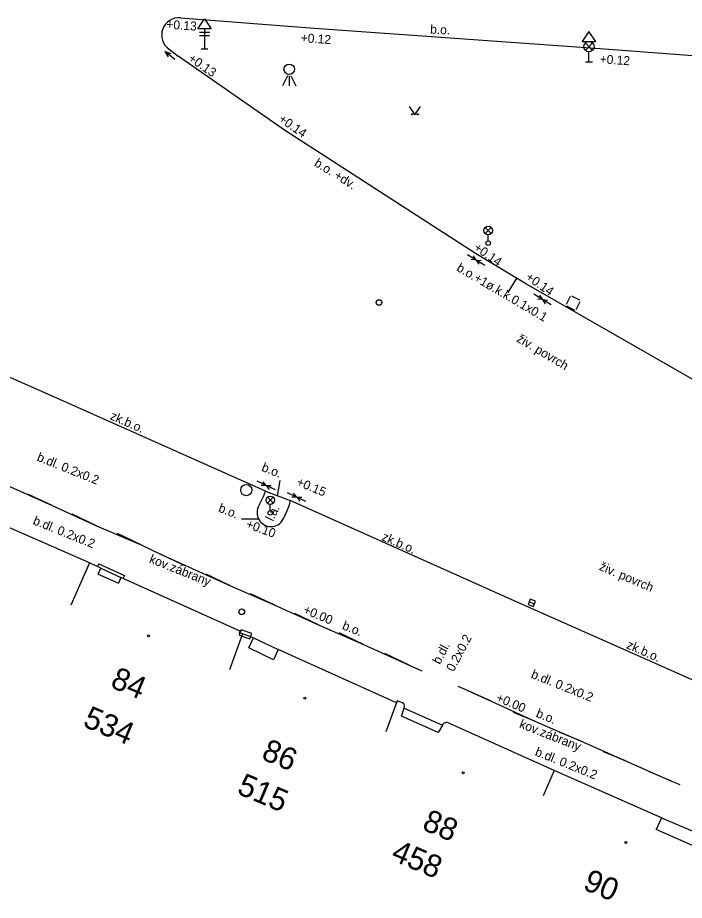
# Model space of a CAD drawing. Extents: x -596069 to -595683, y -1161832 to -1161593.
# Drawn here: x -596003.49 to -595973.78, y -1161680.47 to -1161641.11 of the extents above; entities that cross this region are included whole.
import ezdxf

# ---------------------------------------------------------------- set-up
doc = ezdxf.new("R2010")
doc.units = 0
for name, color, linetype in [('Vrstva 14', 7, 'Continuous'), ('Vrstva 15', 7, 'Continuous'), ('Vrstva 23', 7, 'Continuous'), ('Vrstva 24', 7, 'Continuous'), ('Vrstva 25', 7, 'Continuous'), ('Vrstva 29', 7, 'Continuous'), ('Vrstva 4', 7, 'Continuous'), ('Vrstva 43', 7, 'Continuous'), ('Vrstva 44', 7, 'Continuous'), ('Vrstva 49', 7, 'Continuous'), ('Vrstva 5', 7, 'Continuous'), ('Vrstva 50', 7, 'Continuous'), ('Vrstva 7', 7, 'Continuous')]:
    doc.layers.add(name, color=color, linetype=linetype)

msp = doc.modelspace()

# ---------------------------------------------------------------- linework, layer by layer
at = {"layer": 'Vrstva 14'}
msp.add_lwpolyline([(-595986.039, -1161645.069), (-595985.789, -1161645.444), (-595985.539, -1161645.069)], dxfattribs=at)
for centre in [(-595985.914, -1161645.419), (-595985.664, -1161645.419)]:
    msp.add_circle(centre, 0.025, dxfattribs=at)
at = {"layer": 'Vrstva 15'}
for centre in [(-595997.659, -1161668.68), (-595990.699, -1161671.454), (-595983.641, -1161674.788), (-595976.389, -1161677.888)]:
    msp.add_circle(centre, 0.0438, dxfattribs=at)
at = {"layer": 'Vrstva 23'}
for p, q in [((-595978.866, -1161653.544), (-595979.05, -1161653.899)), ((-595978.443, -1161653.706), (-595978.799, -1161653.523)), ((-595979.028, -1161653.967), (-595978.673, -1161654.15)), ((-595978.606, -1161654.129), (-595978.422, -1161653.774))]:
    msp.add_line(p, q, dxfattribs=at)
msp.add_circle((-595987.39, -1161653.81), 0.125, dxfattribs=at)
at = {"layer": 'Vrstva 24'}
msp.add_circle((-595993.506, -1161667.602), 0.125, dxfattribs=at)
at = {"layer": 'Vrstva 25'}
msp.add_line((-595980.695, -1161667.161), (-595980.463, -1161667.253), dxfattribs=at)
msp.add_lwpolyline([(-595980.741, -1161667.278), (-595980.508, -1161667.369), (-595980.417, -1161667.136), (-595980.65, -1161667.045)], close=True, dxfattribs=at)
msp.add_circle((-595993.304, -1161662.176), 0.25, dxfattribs=at)
at = {"layer": 'Vrstva 29'}
for p, q in [((-595982.656, -1161650.732), (-595982.392, -1161650.468)), ((-595982.388, -1161650.731), (-595982.652, -1161650.466)), ((-595982.524, -1161651.063), (-595982.524, -1161650.788)), ((-595992.366, -1161662.76), (-595992.102, -1161662.496)), ((-595992.098, -1161662.759), (-595992.362, -1161662.494)), ((-595992.234, -1161663.091), (-595992.234, -1161662.816))]:
    msp.add_line(p, q, dxfattribs=at)
msp.add_lwpolyline([(-595993.617, -1161668.642), (-595993.147, -1161668.813), (-595993.061, -1161668.578), (-595993.531, -1161668.407)], close=True, dxfattribs=at)
for centre, radius in [((-595982.524, -1161650.6), 0.188), ((-595982.524, -1161651.163), 0.1), ((-595992.234, -1161662.629), 0.188), ((-595992.234, -1161663.191), 0.1)]:
    msp.add_circle(centre, radius, dxfattribs=at)
at = {"layer": 'Vrstva 4'}
for p, q in [((-596000.293, -1161665.422), (-596004.908, -1161663.397)), ((-595999.782, -1161665.657), (-596000.293, -1161665.422)), ((-595999.901, -1161665.919), (-595999.781, -1161665.655)), ((-595998.888, -1161666.067), (-595999.004, -1161666.324)), ((-595993.583, -1161668.471), (-595998.888, -1161666.067)), ((-595993.583, -1161668.471), (-595993.616, -1161668.544)), ((-595993.471, -1161668.584), (-595993.616, -1161668.544)), ((-595993.471, -1161668.584), (-595994.047, -1161670.189))]:
    msp.add_line(p, q, dxfattribs=at)
for points in [[(-596000.293, -1161665.422), (-596001.12, -1161667.308)], [(-595999.87, -1161665.461), (-595999.928, -1161665.588)], [(-595999.87, -1161665.461), (-595998.739, -1161665.982)], [(-595999.781, -1161665.655), (-595998.888, -1161666.067)], [(-595998.739, -1161665.982), (-595998.794, -1161666.103)], [(-595992.975, -1161668.762), (-595993.471, -1161668.584)], [(-595993.192, -1161669.213), (-595992.975, -1161668.762)], [(-595992.975, -1161668.762), (-595991.89, -1161669.283)], [(-595991.89, -1161669.283), (-595992.096, -1161669.739)], [(-595986.614, -1161671.669), (-595991.89, -1161669.283)], [(-595986.58, -1161671.575), (-595987.078, -1161672.953)], [(-595986.337, -1161671.663), (-595986.58, -1161671.575)], [(-595986.389, -1161672.252), (-595986.269, -1161671.893)], [(-595986.269, -1161671.893), (-595984.566, -1161672.655)], [(-595984.566, -1161672.655), (-595984.757, -1161672.989)], [(-595979.585, -1161674.683), (-595984.275, -1161672.575)], [(-595979.585, -1161674.683), (-595980.078, -1161675.805)], [(-595974.8, -1161676.786), (-595979.585, -1161674.683)], [(-595974.8, -1161676.786), (-595975.033, -1161677.317)], [(-595974.8, -1161676.786), (-595972.91, -1161677.594)]]:
    msp.add_lwpolyline(points, dxfattribs=at)
for centre, radius, start, end in [((-595986.42, -1161671.813), 0.171, 331.9529, 60.988), ((-595984.384, -1161672.748), 0.205, 57.8678, 152.8755)]:
    msp.add_arc(centre, radius, start, end, dxfattribs=at)
at = {"layer": 'Vrstva 44'}
for p, q in [((-595995.382, -1161641.756), (-595994.934, -1161641.756)), ((-595995.162, -1161641.606), (-595995.162, -1161642.506)), ((-595995.382, -1161641.906), (-595994.939, -1161641.906)), ((-595995.312, -1161642.506), (-595995.012, -1161642.506)), ((-595977.88, -1161642.232), (-595978.18, -1161642.576)), ((-595978.18, -1161642.232), (-595977.88, -1161642.576)), ((-595978.03, -1161643.082), (-595978.03, -1161642.632)), ((-595978.18, -1161643.082), (-595977.88, -1161643.082)), ((-595991.466, -1161643.705), (-595991.692, -1161644.157)), ((-595991.392, -1161643.707), (-595991.392, -1161644.157)), ((-595991.317, -1161643.705), (-595991.092, -1161644.157)), ((-596001.954, -1161662.87), (-596003.041, -1161662.353)), ((-595999.975, -1161663.763), (-596001.062, -1161663.246)), ((-595997.953, -1161664.626), (-595999.04, -1161664.109)), ((-595996.044, -1161665.555), (-595997.131, -1161665.038)), ((-595994.007, -1161666.448), (-595995.094, -1161665.931)), ((-595992.025, -1161667.312), (-595993.112, -1161666.795)), ((-595990.056, -1161668.196), (-595991.143, -1161667.679)), ((-595988.083, -1161669.062), (-595989.17, -1161668.545)), ((-595986.049, -1161669.986), (-595987.136, -1161669.469)), ((-595982.389, -1161671.59), (-595983.45, -1161671.116)), ((-595980.409, -1161672.491), (-595981.389, -1161672.089)), ((-595978.385, -1161673.366), (-595979.365, -1161672.964)), ((-595976.402, -1161674.248), (-595977.382, -1161673.846)), ((-595974.35, -1161675.148), (-595975.33, -1161674.746))]:
    msp.add_line(p, q, dxfattribs=at)
msp.add_lwpolyline([(-595995.462, -1161641.611), (-595995.162, -1161641.156), (-595994.862, -1161641.611)], close=True, dxfattribs=at)
msp.add_lwpolyline([(-595978.33, -1161642.176), (-595977.73, -1161642.176), (-595978.03, -1161641.726), (-595978.33, -1161642.176)], dxfattribs=at)
for centre, radius in [((-595978.03, -1161642.404), 0.228), ((-595991.392, -1161643.412), 0.234)]:
    msp.add_circle(centre, radius, dxfattribs=at)
at = {"layer": 'Vrstva 49'}
for p, q in [((-595996.489, -1161642.971), (-595996.928, -1161642.617)), ((-595996.928, -1161642.617), (-595996.661, -1161642.707)), ((-595996.928, -1161642.617), (-595996.78, -1161642.858)), ((-595982.679, -1161652.158), (-595983.443, -1161651.68)), ((-595983.061, -1161651.919), (-595983.284, -1161651.897)), ((-595983.061, -1161651.919), (-595983.179, -1161651.73)), ((-595983.061, -1161651.919), (-595982.946, -1161652.108)), ((-595983.061, -1161651.919), (-595982.839, -1161651.94)), ((-595981.265, -1161652.729), (-595981.652, -1161653.359)), ((-595979.717, -1161653.918), (-595980.481, -1161653.44)), ((-595980.099, -1161653.679), (-595980.217, -1161653.49)), ((-595980.099, -1161653.679), (-595980.322, -1161653.657)), ((-595980.099, -1161653.679), (-595979.984, -1161653.868)), ((-595980.099, -1161653.679), (-595979.877, -1161653.7)), ((-595992.009, -1161662.171), (-595992.821, -1161661.781)), ((-595992.415, -1161661.976), (-595992.553, -1161661.801)), ((-595991.908, -1161662.433), (-595991.79, -1161661.744)), ((-595992.415, -1161661.976), (-595992.639, -1161661.978)), ((-595992.415, -1161661.976), (-595992.192, -1161661.972)), ((-595992.415, -1161661.976), (-595992.28, -1161662.152)), ((-595990.65, -1161662.684), (-595991.462, -1161662.294)), ((-595991.056, -1161662.489), (-595991.28, -1161662.491)), ((-595991.056, -1161662.489), (-595991.194, -1161662.314)), ((-595991.056, -1161662.489), (-595990.833, -1161662.485)), ((-595991.056, -1161662.489), (-595990.921, -1161662.665)), ((-595992.755, -1161663.477), (-595993.523, -1161663.477))]:
    msp.add_line(p, q, dxfattribs=at)
at = {"layer": 'Vrstva 5'}
for p, q in [((-595999.901, -1161665.919), (-595999.004, -1161666.324)), ((-595992.096, -1161669.739), (-595993.192, -1161669.213)), ((-595984.757, -1161672.989), (-595986.389, -1161672.252)), ((-595973.15, -1161678.142), (-595975.033, -1161677.317))]:
    msp.add_line(p, q, dxfattribs=at)
at = {"layer": 'Vrstva 7'}
for p, q in [((-596003.946, -1161661.974), (-596001.954, -1161662.87)), ((-595992.446, -1161662.231), (-595991.352, -1161662.644)), ((-596001.954, -1161662.87), (-595999.975, -1161663.763)), ((-595999.975, -1161663.763), (-595997.953, -1161664.626)), ((-595997.953, -1161664.626), (-595997.131, -1161665.038)), ((-595997.131, -1161665.038), (-595994.007, -1161666.448)), ((-595986.049, -1161669.986), (-595985.483, -1161670.239)), ((-595983.45, -1161671.116), (-595983.863, -1161670.931)), ((-595983.45, -1161671.116), (-595982.389, -1161671.59)), ((-595982.389, -1161671.59), (-595980.409, -1161672.491)), ((-595980.409, -1161672.491), (-595978.385, -1161673.366)), ((-595978.385, -1161673.366), (-595976.402, -1161674.248)), ((-595976.402, -1161674.248), (-595974.35, -1161675.148)), ((-595974.35, -1161675.148), (-595973.985, -1161675.311))]:
    msp.add_line(p, q, dxfattribs=at)
for points in [[(-595996.237, -1161641.113), (-595990.261, -1161641.577), (-595977.331, -1161642.507), (-595967.899, -1161643.218), (-595954.03, -1161643.987)], [(-595996.746, -1161642.51), (-595996.335, -1161642.832)], [(-595970.132, -1161659.112), (-595980.814, -1161653), (-595983.088, -1161651.633), (-595991.597, -1161646.128), (-595996.335, -1161642.832)], [(-595992.773, -1161662.939), (-595992.538, -1161662.463), (-595992.446, -1161662.231), (-596001.752, -1161658.08), (-596017.691, -1161651.031), (-596021.958, -1161649.351)], [(-595991.352, -1161662.644), (-595991.411, -1161662.895), (-595991.632, -1161663.42)], [(-595963.2, -1161675.22), (-595965.37, -1161674.25), (-595965.783, -1161674.06), (-595966.468, -1161673.744), (-595974.666, -1161670.081), (-595981.362, -1161667.113), (-595991.352, -1161662.644)], [(-595994.007, -1161666.448), (-595992.025, -1161667.312), (-595990.056, -1161668.196), (-595988.083, -1161669.062), (-595986.049, -1161669.986)]]:
    msp.add_lwpolyline(points, dxfattribs=at)
for centre, radius, start, end in [((-595996.306, -1161641.879), 0.769, 84.8846, 235.0768), ((-595992.204, -1161663.182), 0.619, 156.889, 337.3943)]:
    msp.add_arc(centre, radius, start, end, dxfattribs=at)

# ---------------------------------------------------------------- texts
at = {"layer": 'Vrstva 43'}
for s, p in [('84', (-595999.412, -1161670.945)), ('534', (-596000.633, -1161672.691)), ('86', (-595992.682, -1161674.152)), ('515', (-595993.768, -1161675.691)), ('88', (-595985.517, -1161677.293)), ('458', (-595986.903, -1161678.651)), ('90', (-595978.348, -1161679.959))]:
    msp.add_text(s, height=1, rotation=337, dxfattribs=at).set_placement(p)
at = {"layer": 'Vrstva 49'}
for s, rotation, p in [('b.o.', 357.2707, (-595985.116, -1161641.82)), ('b.o. +dv.', 327.905, (-595990.31, -1161647.691)), ('b.o.+1ø.k.k.0.1x0.1', 329.595, (-595983.966, -1161652.372)), ('živ. povrch', 329.0295, (-595981.29, -1161655.528)), ('zk.b.o.', 336.3516, (-595999.41, -1161659.008)), ('b.dl. 0.2x0.2', 338.0264, (-596002.667, -1161660.852)), ('b.o.', 338.3556, (-595992.656, -1161661.31)), ('b.o.', 338.3168, (-595994.581, -1161663.124)), ('l.a.', 63.8647, (-595992.113, -1161663.595)), ('b.dl. 0.2x0.2', 338.0264, (-596002.844, -1161663.685)), ('zk.b.o.', 336.3516, (-595987.301, -1161664.395)), ('kov.zábrany', 338.3168, (-595997.661, -1161665.397)), ('živ. povrch', 336.8591, (-595977.608, -1161665.723)), ('b.o.', 338.3168, (-595989.06, -1161668.366)), ('0.2x0.2', 62.1022, (-595984.061, -1161670.303)), ('b.dl.', 62.1022, (-595984.68, -1161669.975)), ('zk.b.o.', 336.3516, (-595976.394, -1161669.217)), ('b.dl. 0.2x0.2', 338.0264, (-595980.643, -1161670.536)), ('b.o.', 338.3168, (-595980.421, -1161672.282)), ('kov.zábrany', 338.3168, (-595981.165, -1161672.753)), ('b.dl. 0.2x0.2', 338.0264, (-595980.466, -1161673.996))]:
    msp.add_text(s, height=0.4, rotation=rotation, dxfattribs=at).set_placement(p)
at = {"layer": 'Vrstva 50'}
for s, rotation, p in [('+0.13', 356.173, (-595996.875, -1161641.602)), ('+0.12', 356.173, (-595990.889, -1161642.2)), ('+0.13', 325.323, (-595995.927, -1161643.009)), ('+0.12', 356.173, (-595977.564, -1161643.144)), ('+0.14', 325.323, (-595991.9, -1161645.713)), ('+0.14', 325.323, (-595983.2, -1161651.446)), ('+0.14', 325.323, (-595980.887, -1161652.765)), ('+0.15', 337.7664, (-595991.101, -1161661.96)), ('+0.10', 339.9617, (-595993.354, -1161663.844)), ('+0.00', 337.063, (-595990.802, -1161667.653)), ('+0.00', 337.063, (-595982.205, -1161671.578))]:
    msp.add_text(s, height=0.4, rotation=rotation, dxfattribs=at).set_placement(p)

doc.saveas('drawing.dxf')
